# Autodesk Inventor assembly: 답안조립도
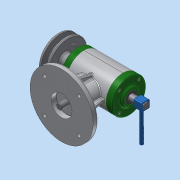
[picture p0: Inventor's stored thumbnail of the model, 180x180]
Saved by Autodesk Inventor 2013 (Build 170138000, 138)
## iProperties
Created: 2017-02
Part Number: 답안조립도
Document SubType Name: Assembly
Designer: dgall
Mass: 1814.1 g
Surface Area: 1453.46 cm^2
Volume: 463.015 cm^3
Density: 3.91801 g/cm^3
Author: dgall
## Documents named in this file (16)
- C:\Users\dgall\Desktop\370207V1030\답안조립도.iam
- C:\Users\dgall\Desktop\370207V1030\본체.ipt
- C:\Users\dgall\Desktop\370207V1030\V벨트풀리.ipt
- C:\Users\dgall\Desktop\370207V1030\가변스프링.ipt
- C:\Users\dgall\Desktop\370207V1030\뒤커버.ipt
- C:\Users\dgall\Desktop\370207V1030\레버.ipt
- C:\Users\dgall\Desktop\370207V1030\멈춤나사 M3x8.ipt
- C:\Users\dgall\Desktop\370207V1030\베어링 6201.ipt
- C:\Users\dgall\Desktop\370207V1030\베어링 6202.ipt
- C:\Users\dgall\Desktop\370207V1030\본체상부커버.ipt
- C:\Users\dgall\Desktop\370207V1030\볼트 M3x0.5x8.ipt
- C:\Users\dgall\Desktop\370207V1030\슬라이드.ipt
- C:\Users\dgall\Desktop\370207V1030\앞커버.ipt
- C:\Users\dgall\Desktop\370207V1030\오일실 12 22 7.ipt
- C:\Users\dgall\Desktop\370207V1030\키 4 x 4 x 18.ipt
- C:\Users\dgall\Desktop\370207V1030\편심축.ipt
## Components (2 placed, 2 different names)
1. V벨트풀리:1
2. 가변스프링:1
